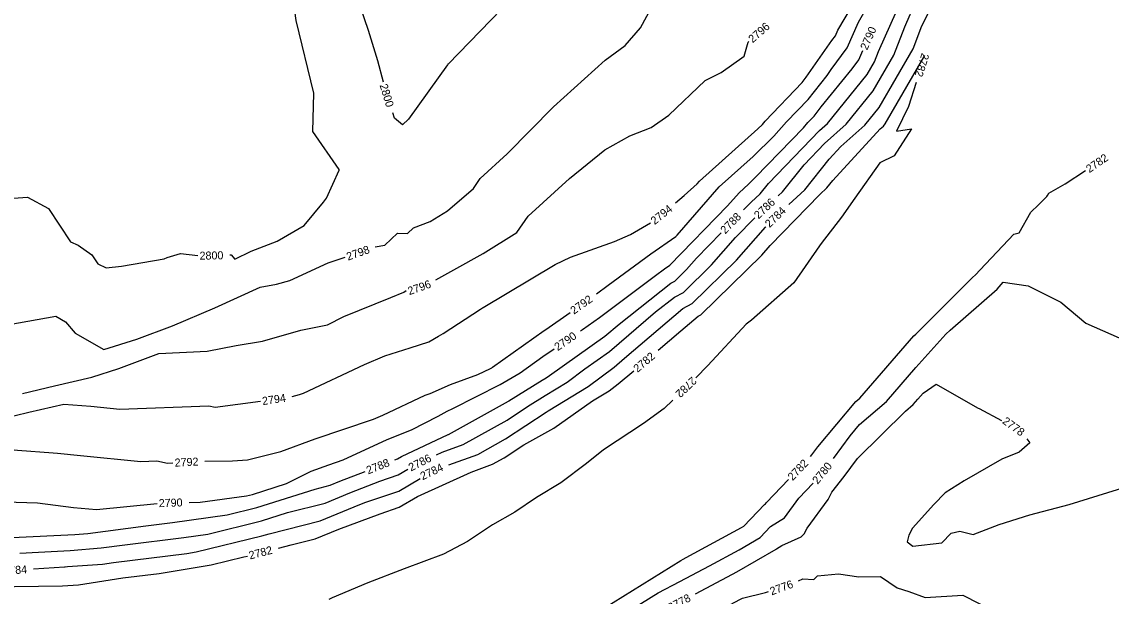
# Model space of a CAD drawing. Extents: x 1326424 to 1329294, y 1001359 to 1003823.
# Drawn here: x 1328510.5 to 1328782.8, y 1001806.2 to 1001949.6 of the extents above; entities that cross this region are included whole.
import ezdxf

# ---------------------------------------------------------------- set-up
doc = ezdxf.new("R2010")
doc.units = 0
doc.layers.add('Prop Rem of Exist Asph Pvmt', color=7, linetype='Continuous')
doc.layers.add('Scratch_Level_3', color=7, linetype='Continuous')

msp = doc.modelspace()

# ---------------------------------------------------------------- linework, layer by layer
at = {"layer": 'Prop Rem of Exist Asph Pvmt'}
for points in [[(1328600.92, 1001934.54), (1328599.51, 1001939.88), (1328597.17, 1001947.45), (1328595.24, 1001953.02), (1328587.81, 1001971.03), (1328587.62, 1001976.02), (1328584.27, 1001990.87), (1328584.12, 1001995.8), (1328586.73, 1002006.74), (1328587.94, 1002009.4), (1328589.07, 1002010.29), (1328590.21, 1002010.83), (1328604.39, 1002021.28), (1328604.71, 1002021.4), (1328604.9, 1002021.47), (1328605.19, 1002021.57), (1328605.84, 1002021.82)], [(1328670.27, 1001993.58), (1328665.62, 1001991.82), (1328664.55, 1001990.95), (1328663.56, 1001989.87), (1328650.93, 1001978.48), (1328642.59, 1001966.08), (1328641.07, 1001963.86), (1328617.08, 1001939.07), (1328617.05, 1001939.03), (1328616.94, 1001938.88), (1328607.22, 1001925.3), (1328605.67, 1001923.86), (1328603.72, 1001925.58), (1328603.26, 1001926.9)], [(1328562.54, 1001891.43), (1328562.83, 1001891.45), (1328563.82, 1001890.38), (1328567.9, 1001892.31), (1328574.38, 1001894.86), (1328581.14, 1001898.8), (1328585.97, 1001904.6), (1328586.7, 1001905.62), (1328589.85, 1001912.58), (1328589.86, 1001912.61), (1328589.82, 1001912.78), (1328583.28, 1001922.21), (1328583.54, 1001931.82), (1328579.11, 1001949.97), (1328578.13, 1001957.28), (1328574.3, 1001971.96)], [(1328483.91, 1001926.36), (1328489.64, 1001916.83), (1328485.71, 1001905.86), (1328486.23, 1001905.1), (1328504.83, 1001905.32), (1328511.95, 1001905.81), (1328517.18, 1001903.01), (1328522.69, 1001894.66), (1328524.62, 1001893.84), (1328528.08, 1001891.46), (1328529.55, 1001889.22), (1328531.61, 1001888.19), (1328535.43, 1001888.62), (1328546.11, 1001890.43), (1328546.85, 1001890.73), (1328550.22, 1001891.78), (1328554.56, 1001891.3)], [(1328713.37, 1001840.59), (1328717.57, 1001846.26), (1328719.93, 1001849.06), (1328726.64, 1001854.84), (1328733.99, 1001863.27), (1328741.49, 1001871.58), (1328742.54, 1001872.63), (1328754.3, 1001882.89), (1328755.81, 1001884.57), (1328762.08, 1001883.73), (1328770.2, 1001879.63), (1328776.43, 1001874.37), (1328784.83, 1001870.72), (1328788.03, 1001871.35), (1328790.74, 1001871.33)], [(1328624.32, 1001782.17), (1328627.56, 1001783.09), (1328628.23, 1001784), (1328636.71, 1001788.77), (1328645.92, 1001793.25), (1328655.03, 1001797.94), (1328665.39, 1001804.43), (1328669.57, 1001807.04), (1328674.99, 1001809.84), (1328682.39, 1001813.78), (1328689.83, 1001817.8), (1328695.05, 1001820.81), (1328697.68, 1001823.55), (1328701.16, 1001825.76), (1328704.74, 1001830.68), (1328708.31, 1001834.4)]]:
    msp.add_lwpolyline(points, dxfattribs=at)
at = {"layer": 'Scratch_Level_3'}
for points in [[(1328699.54, 1001906.14), (1328700.66, 1001907.18), (1328706.05, 1001913.93), (1328711.17, 1001919.23), (1328716.57, 1001924.03), (1328723.34, 1001932.36), (1328728.49, 1001941.26), (1328731.22, 1001948.41), (1328732.58, 1001951.46), (1328733.05, 1001952.46), (1328739.31, 1001963.54), (1328738.61, 1001974.44), (1328738.72, 1001974.77), (1328738.68, 1001975.02), (1328738.54, 1001976.48), (1328738.97, 1001988.91), (1328738.53, 1001992.86)], [(1328702.25, 1001904), (1328706.21, 1001907.66), (1328712.33, 1001915.32), (1328715.24, 1001918.49), (1328721.22, 1001923.79), (1328724.84, 1001928.25), (1328733.3, 1001942.85), (1328735.49, 1001948.59), (1328739.03, 1001955.71), (1328743.13, 1001962.96), (1328742.74, 1001969.02), (1328743.23, 1001975.26), (1328742.9, 1001982.79), (1328743.11, 1001988.9), (1328742.95, 1001990.37)], [(1328690.93, 1001902.65), (1328692.84, 1001904.61), (1328695.11, 1001906.7), (1328697.17, 1001909.28), (1328709.9, 1001922.47), (1328711.92, 1001924.26), (1328721.84, 1001936.48), (1328723.68, 1001939.67), (1328724.66, 1001942.23), (1328729.22, 1001952.43), (1328730.79, 1001955.78), (1328735.5, 1001964.11), (1328734.97, 1001972.31), (1328735.51, 1001973.96), (1328735.32, 1001975.25), (1328734.61, 1001982.67), (1328734.76, 1001987.2)], [(1328673.93, 1001904.44), (1328676.1, 1001906.27), (1328679.31, 1001909.13), (1328679.92, 1001909.82), (1328694.46, 1001922.9), (1328695.62, 1001924.02), (1328696.31, 1001924.82), (1328705.53, 1001934.44), (1328706.58, 1001935.77), (1328712.99, 1001944.97), (1328713.87, 1001946.16), (1328714.5, 1001947.58), (1328721.03, 1001958.7), (1328723.97, 1001965.68), (1328724, 1001965.74), (1328724.05, 1001965.83), (1328724.04, 1001965.92), (1328725.9, 1001971.54), (1328725.25, 1001975.95), (1328725.22, 1001976.25), (1328723.9, 1001982.4), (1328723.38, 1001985.1)], [(1328598.85, 1001893.47), (1328601.23, 1001893.81), (1328604.45, 1001896.88), (1328606.96, 1001896.75), (1328608.41, 1001898.17), (1328612.56, 1001899.79), (1328616.94, 1001902.45), (1328623.39, 1001908.02), (1328625.09, 1001910.46), (1328631.87, 1001916.63), (1328643.39, 1001928.43), (1328656.3, 1001940.08), (1328661.33, 1001943.73), (1328665.13, 1001948.09), (1328668.86, 1001954.87), (1328672.87, 1001957.4)], [(1328654.14, 1001881.67), (1328657.1, 1001883.89), (1328667.73, 1001891.71), (1328674.01, 1001896.04), (1328674.3, 1001896.33), (1328684.86, 1001908.38), (1328693.29, 1001915.97), (1328698.53, 1001921.06), (1328701.65, 1001924.65), (1328707.03, 1001930.26), (1328711.78, 1001936.26), (1328712.82, 1001937.75), (1328716.79, 1001943.13), (1328719.63, 1001949.57), (1328721.99, 1001953.6)], [(1328614.01, 1001885.17), (1328618.53, 1001887.68), (1328625.86, 1001891.73), (1328634.24, 1001897.03), (1328637.09, 1001901.12), (1328647.44, 1001910.52), (1328656.27, 1001917.68), (1328662.47, 1001921.18), (1328667.87, 1001923.22), (1328672.28, 1001926.34), (1328681.29, 1001934.98), (1328685.32, 1001937), (1328691.04, 1001941.02), (1328692.04, 1001944.57), (1328692.22, 1001944.73)], [(1328650.18, 1001872.45), (1328650.67, 1001872.78), (1328654.92, 1001875.76), (1328668.9, 1001886.24), (1328671.18, 1001887.92), (1328672.53, 1001888.85), (1328686.88, 1001903.63), (1328689.8, 1001906.95), (1328692.12, 1001909.04), (1328693.93, 1001910.8), (1328705.88, 1001923.19), (1328706.99, 1001924.48), (1328708.54, 1001926.09), (1328710.36, 1001928.38), (1328718.09, 1001937.92), (1328719.71, 1001940.11), (1328720.73, 1001942.43)], [(1328669.57, 1001867.61), (1328675.28, 1001872.43), (1328679.59, 1001876.09), (1328680.28, 1001876.45), (1328695.47, 1001891.31), (1328697.6, 1001893.74), (1328709.97, 1001906.48), (1328711.76, 1001908.14), (1328713.27, 1001910.03), (1328725.09, 1001922.86), (1328725.87, 1001923.55), (1328726.35, 1001924.13), (1328736.25, 1001941.23)], [(1328734.09, 1001934.43), (1328732.11, 1001928.48), (1328729.17, 1001922.32), (1328732.93, 1001922.93), (1328728.6, 1001916.19), (1328724.95, 1001914.43), (1328718.7, 1001905.55), (1328715.38, 1001900.83), (1328710.35, 1001894.24), (1328709.92, 1001893.69), (1328703.49, 1001884.47), (1328692.91, 1001875.1), (1328691.56, 1001874.14), (1328681.97, 1001863.77), (1328679.02, 1001860.72)], [(1328707.66, 1001841.09), (1328708, 1001841.51), (1328709.45, 1001843.47), (1328719.02, 1001854.82), (1328719.99, 1001855.66), (1328733.52, 1001871.17), (1328733.95, 1001871.66), (1328748.14, 1001885.76), (1328748.91, 1001886.43), (1328750.05, 1001887.69), (1328758.5, 1001896.62), (1328759.78, 1001896.89), (1328762.7, 1001902.07), (1328764.63, 1001903.94), (1328766.72, 1001906), (1328766.86, 1001906.25), (1328767.22, 1001906.87), (1328771.28, 1001909.17), (1328776.37, 1001912.52)], [(1328578.1, 1001856.06), (1328579.94, 1001856.52), (1328580.93, 1001856.91), (1328596.15, 1001864.07), (1328601.26, 1001866.18), (1328607.58, 1001868.2), (1328612.25, 1001869.71), (1328614.65, 1001871.14), (1328615.83, 1001871.82), (1328625.15, 1001877.88), (1328625.72, 1001878.23), (1328625.81, 1001878.3), (1328643.82, 1001889.05), (1328647.71, 1001890.84), (1328658.64, 1001894.73), (1328662.7, 1001896.48), (1328667.69, 1001899.46)], [(1328614.18, 1001841.52), (1328615.59, 1001842.17), (1328620.85, 1001844.08), (1328631.82, 1001850.18), (1328636.91, 1001853.55), (1328641.37, 1001856.29), (1328646.84, 1001859.62), (1328651.26, 1001862.94), (1328657.4, 1001867.28), (1328668.95, 1001877.16), (1328673.64, 1001880.85), (1328675.9, 1001882.05), (1328682.94, 1001888.93), (1328688.91, 1001895.74), (1328693.71, 1001900.66)], [(1328603.81, 1001840.26), (1328604.45, 1001840.48), (1328605.46, 1001841.08), (1328617.08, 1001846.53), (1328617.17, 1001846.56), (1328632.19, 1001854.9), (1328632.25, 1001854.95), (1328640.62, 1001860.1), (1328641.6, 1001860.7), (1328642.39, 1001861.29), (1328656.24, 1001871.08), (1328659.82, 1001874.14), (1328672.76, 1001884.34), (1328673.72, 1001884.85), (1328676.68, 1001887.74), (1328679.19, 1001890.61), (1328685.35, 1001896.92)], [(1328617.26, 1001838.97), (1328624.52, 1001841.6), (1328631.45, 1001845.45), (1328641.57, 1001852.15), (1328642.12, 1001852.49), (1328652.07, 1001858.54), (1328658.55, 1001863.41), (1328661.19, 1001865.64), (1328675.78, 1001878.03), (1328678.09, 1001879.25), (1328689.2, 1001890.12), (1328696.43, 1001898.36), (1328696.5, 1001898.44)], [(1328498.85, 1001872.5), (1328519.08, 1001876.08), (1328521.42, 1001874.66), (1328523.86, 1001871.84), (1328531.03, 1001867.75), (1328539.31, 1001870.4), (1328548.23, 1001873.74), (1328558.77, 1001878.21), (1328570.15, 1001883.38), (1328574.19, 1001884.07), (1328577.53, 1001885.05), (1328587.12, 1001889.41), (1328591.34, 1001890.81)], [(1328510.7, 1001856.77), (1328518.68, 1001858.71), (1328528.05, 1001860.89), (1328534.78, 1001863.05), (1328544.79, 1001866.79), (1328556.87, 1001867.34), (1328564.09, 1001868.75), (1328570.72, 1001869.88), (1328580.25, 1001872.66), (1328586.94, 1001873.99), (1328591, 1001876.01), (1328602.78, 1001880.78), (1328605.99, 1001882.11), (1328606.61, 1001882.56)], [(1328556.31, 1001839.9), (1328563.23, 1001840.02), (1328566.97, 1001840.23), (1328575.25, 1001842.33), (1328583.88, 1001845.51), (1328598.15, 1001850.3), (1328598.4, 1001850.41), (1328600.78, 1001851.37), (1328611.34, 1001856.37), (1328612.62, 1001856.77), (1328617.71, 1001859.03), (1328624.48, 1001861.57), (1328627.67, 1001863.07), (1328628.03, 1001863.25), (1328628.18, 1001863.34), (1328641.08, 1001872.5), (1328641.51, 1001872.8), (1328647.6, 1001877.06)], [(1328552.35, 1001829.6), (1328555.11, 1001829.65), (1328566.67, 1001831.25), (1328568.18, 1001831.62), (1328576.67, 1001834.33), (1328582.88, 1001837.4), (1328587.26, 1001839.01), (1328590.88, 1001840.23), (1328601.88, 1001845.3), (1328607.97, 1001847.74), (1328614.62, 1001851.16), (1328616.86, 1001852.42), (1328618.29, 1001853.09), (1328630.12, 1001859.08), (1328635.07, 1001861.99), (1328640.73, 1001866.01), (1328643.57, 1001867.95)], [(1328574.67, 1001818.21), (1328577.85, 1001819.02), (1328583.84, 1001820.54), (1328589.74, 1001822.95), (1328600.09, 1001826.77), (1328604.88, 1001828.39), (1328609.47, 1001831.1), (1328622.87, 1001837.19), (1328628.2, 1001839.12), (1328631.08, 1001840.72), (1328635.99, 1001843.97), (1328643.5, 1001848.18), (1328653.15, 1001854.94), (1328657.31, 1001857.47), (1328659.62, 1001859.2), (1328663.46, 1001862.45)], [(1328678.91, 1001806.76), (1328688.19, 1001811.71), (1328689.23, 1001812.26), (1328699.09, 1001817.95), (1328699.19, 1001818.05), (1328700.47, 1001818.86), (1328705.32, 1001821.03), (1328706.07, 1001821.72), (1328706.84, 1001823.2), (1328712.06, 1001830.37), (1328712.95, 1001832.15), (1328716.08, 1001836.09), (1328719.37, 1001840.53), (1328731.43, 1001852.41), (1328733.3, 1001854.03), (1328734.47, 1001855.36), (1328735.84, 1001856.88), (1328739.09, 1001859.17), (1328749.41, 1001853.26), (1328749.53, 1001853.15), (1328749.77, 1001853.05), (1328755.37, 1001850.09)], [(1328471.04, 1001851.86), (1328477.04, 1001850.3), (1328479.52, 1001850.11), (1328490.38, 1001849.54), (1328499.31, 1001850.38), (1328508.87, 1001851.27), (1328512.31, 1001852.1), (1328521.05, 1001854.14), (1328527.79, 1001853.6), (1328535.08, 1001852.86), (1328557.28, 1001853.71), (1328558.88, 1001853.38), (1328570.19, 1001854.88)], [(1328673.27, 1001855.17), (1328671.09, 1001853.07), (1328665.89, 1001849.34), (1328655.93, 1001842.73), (1328651.67, 1001839.36), (1328645.23, 1001834.48), (1328639.14, 1001830.8), (1328633.78, 1001827.16), (1328628.2, 1001823.97), (1328621.89, 1001819.83), (1328615.9, 1001816.66), (1328606.13, 1001813), (1328596.99, 1001809.54), (1328588.09, 1001805.78), (1328587.29, 1001805.38)], [(1328449.48, 1001850.67), (1328462.61, 1001847.49), (1328464.69, 1001846.51), (1328466.95, 1001845.92), (1328486.51, 1001844.42), (1328488.57, 1001844.31), (1328495.05, 1001844.92), (1328502.25, 1001843.41), (1328509.49, 1001842.65), (1328518.35, 1001842.02), (1328519.42, 1001841.88), (1328525.19, 1001841.35), (1328540.25, 1001839.82), (1328544.26, 1001839.97), (1328546.92, 1001839.43), (1328548.32, 1001839.5)], [(1328761.72, 1001845.47), (1328762.49, 1001844.5), (1328759.8, 1001842.12), (1328755.46, 1001840.4), (1328746.03, 1001835.02), (1328741.32, 1001832.01), (1328738.49, 1001829.07), (1328733.16, 1001823.17), (1328732.22, 1001821.46), (1328731.83, 1001819.73), (1328733.27, 1001818.71), (1328740.49, 1001819.55), (1328742.83, 1001821.89), (1328744.96, 1001822.4), (1328748.27, 1001821.59), (1328754.77, 1001824.1), (1328762.47, 1001826.49), (1328772.32, 1001829.11), (1328786.77, 1001833.58)], [(1328446.42, 1001840.15), (1328451.72, 1001837.09), (1328452.44, 1001836.71), (1328463.89, 1001832.3), (1328467.84, 1001831.66), (1328469.85, 1001831.46), (1328473.93, 1001831.48), (1328489.34, 1001831.59), (1328495.45, 1001830.8), (1328509.12, 1001829.66), (1328514.47, 1001829.49), (1328523.49, 1001828.34), (1328529.18, 1001827.81), (1328544.36, 1001829.32)], [(1328498.53, 1001821.57), (1328501.52, 1001821.18), (1328503.69, 1001820.58), (1328508.13, 1001820.88), (1328523.8, 1001821.57), (1328527.05, 1001821.87), (1328541.56, 1001823.76), (1328548.21, 1001824.58), (1328561.86, 1001826.48), (1328569.3, 1001828.3), (1328583.85, 1001832.93), (1328587.59, 1001833.87), (1328590.06, 1001834.89), (1328596.36, 1001837.36)], [(1328510.04, 1001816.9), (1328514.68, 1001817.21), (1328522.59, 1001817.56), (1328530.41, 1001818.28), (1328536.27, 1001819.04), (1328551.04, 1001820.86), (1328557.05, 1001821.7), (1328570.41, 1001824.97), (1328576.94, 1001827.05), (1328586.34, 1001829.43), (1328592.56, 1001831.97), (1328599.99, 1001834.89), (1328604.59, 1001836.45), (1328607.05, 1001837.9)], [(1328513.48, 1001813.02), (1328521.24, 1001813.54), (1328521.39, 1001813.54), (1328521.99, 1001813.6), (1328530.74, 1001814.19), (1328533.44, 1001814.6), (1328551.79, 1001816.87), (1328554.08, 1001817.24), (1328570.49, 1001821.28), (1328572.35, 1001821.76), (1328585.09, 1001824.99), (1328595.06, 1001829.06), (1328596.53, 1001829.64), (1328604.74, 1001832.42), (1328610.06, 1001835.57)], [(1328617.49, 1001783.68), (1328622.58, 1001785.26), (1328623.49, 1001785.52), (1328623.58, 1001785.64), (1328637.23, 1001793.31), (1328638.91, 1001794.13), (1328654, 1001801.9), (1328655.89, 1001803.09), (1328675.22, 1001815.13), (1328675.8, 1001815.43), (1328676.59, 1001815.85), (1328690.43, 1001823.33), (1328691.01, 1001823.67), (1328696.17, 1001829.06), (1328696.42, 1001829.22), (1328696.68, 1001829.58), (1328702.16, 1001835.29)], [(1328469.41, 1001817.68), (1328471.57, 1001816.09), (1328473.62, 1001815.57), (1328476.5, 1001814.74), (1328484.43, 1001811.21), (1328487.87, 1001811.08), (1328496.65, 1001809.17), (1328500.67, 1001808.06), (1328508.74, 1001808.59), (1328520.68, 1001808.77), (1328524.69, 1001809.04), (1328535.78, 1001810.74), (1328544.88, 1001811.86), (1328557.88, 1001813.98), (1328566.02, 1001815.98), (1328566.92, 1001816.21)], [(1328704.66, 1001810.05), (1328705.71, 1001810.51), (1328708.51, 1001810.35), (1328709.42, 1001811.29), (1328714.62, 1001811.79), (1328719.72, 1001811.03), (1328725.17, 1001811.12), (1328729.28, 1001808.3), (1328732.23, 1001807.34), (1328736.32, 1001805.89), (1328745.7, 1001806.42), (1328757.84, 1001800.28), (1328764.26, 1001798.34), (1328764.38, 1001798.26), (1328769.12, 1001797.75), (1328771.53, 1001798.15), (1328778.87, 1001799.61), (1328789.86, 1001799.27), (1328800.46, 1001799.79), (1328800.79, 1001799.82)], [(1328605.69, 1001768.67), (1328619.38, 1001772.86), (1328619.73, 1001773), (1328623.23, 1001774.12), (1328632.92, 1001776.86), (1328635.57, 1001777.3), (1328639.76, 1001779.41), (1328641.21, 1001781.12), (1328656.68, 1001788.34), (1328660.58, 1001789.83), (1328673.18, 1001796.72), (1328677.32, 1001798.63), (1328690.14, 1001805.42), (1328690.69, 1001805.68), (1328696.39, 1001807.08), (1328697.15, 1001807.32)]]:
    msp.add_lwpolyline(points, dxfattribs=at)

# ---------------------------------------------------------------- texts
at = {"layer": 'Prop Rem of Exist Asph Pvmt'}
for s, rotation, p in [('2800', 286.9675, (1328599.94, 1001933.81)), ('2800', 0.9843, (1328554.98, 1001890.22)), ('2780', 50.7681, (1328709.45, 1001834.01))]:
    msp.add_text(s, height=2, rotation=rotation, dxfattribs=at).set_placement(p)
at = {"layer": 'Scratch_Level_3'}
for s, rotation, p in [('2796', 41.1105, (1328693.19, 1001944.25)), ('2790', 66.2017, (1328721.81, 1001942.41)), ('2782', 252.3542, (1328735.48, 1001941.95)), ('2782', 34.473, (1328777.36, 1001911.82)), ('2786', 43.2475, (1328694.67, 1001900.25)), ('2794', 38.6069, (1328668.7, 1001898.84)), ('2784', 44.0964, (1328697.43, 1001898.08)), ('2788', 45.713, (1328686.35, 1001896.52)), ('2798', 19.5512, (1328592.08, 1001889.97)), ('2796', 19.3935, (1328607.4, 1001881.35)), ('2792', 35.1718, (1328648.52, 1001876.47)), ('2790', 34.282, (1328644.48, 1001867.36)), ('2782', 40.176, (1328664.43, 1001861.95)), ('2782', 223.9768, (1328678.03, 1001861.15)), ('2794', 8.4385, (1328570.76, 1001853.9)), ('2778', 323.9583, (1328755.42, 1001849.51)), ('2792', 2.8475, (1328548.79, 1001838.53)), ('2788', 21.3084, (1328597.11, 1001836.59)), ('2786', 26.877, (1328607.81, 1001837.31)), ('2782', 46.5147, (1328703.19, 1001834.89)), ('2784', 25.3099, (1328610.71, 1001835.12)), ('2790', 1.9914, (1328544.8, 1001828.41)), ('2782', 14.4319, (1328567.58, 1001815.35)), ('2784', 3.8181, (1328505.98, 1001811.52)), ('2776', 19.9417, (1328697.93, 1001806.37)), ('2778', 27.786, (1328672.67, 1001802.33))]:
    msp.add_text(s, height=2, rotation=rotation, dxfattribs=at).set_placement(p)

doc.saveas('drawing.dxf')
